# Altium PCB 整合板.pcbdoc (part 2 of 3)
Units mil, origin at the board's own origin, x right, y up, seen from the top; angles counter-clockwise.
Board outline 5095 x 5568.76 mil, 2 copper layers (Top Layer, Bottom Layer); 124 components, 78 nets, 425 pads, 497 vias.
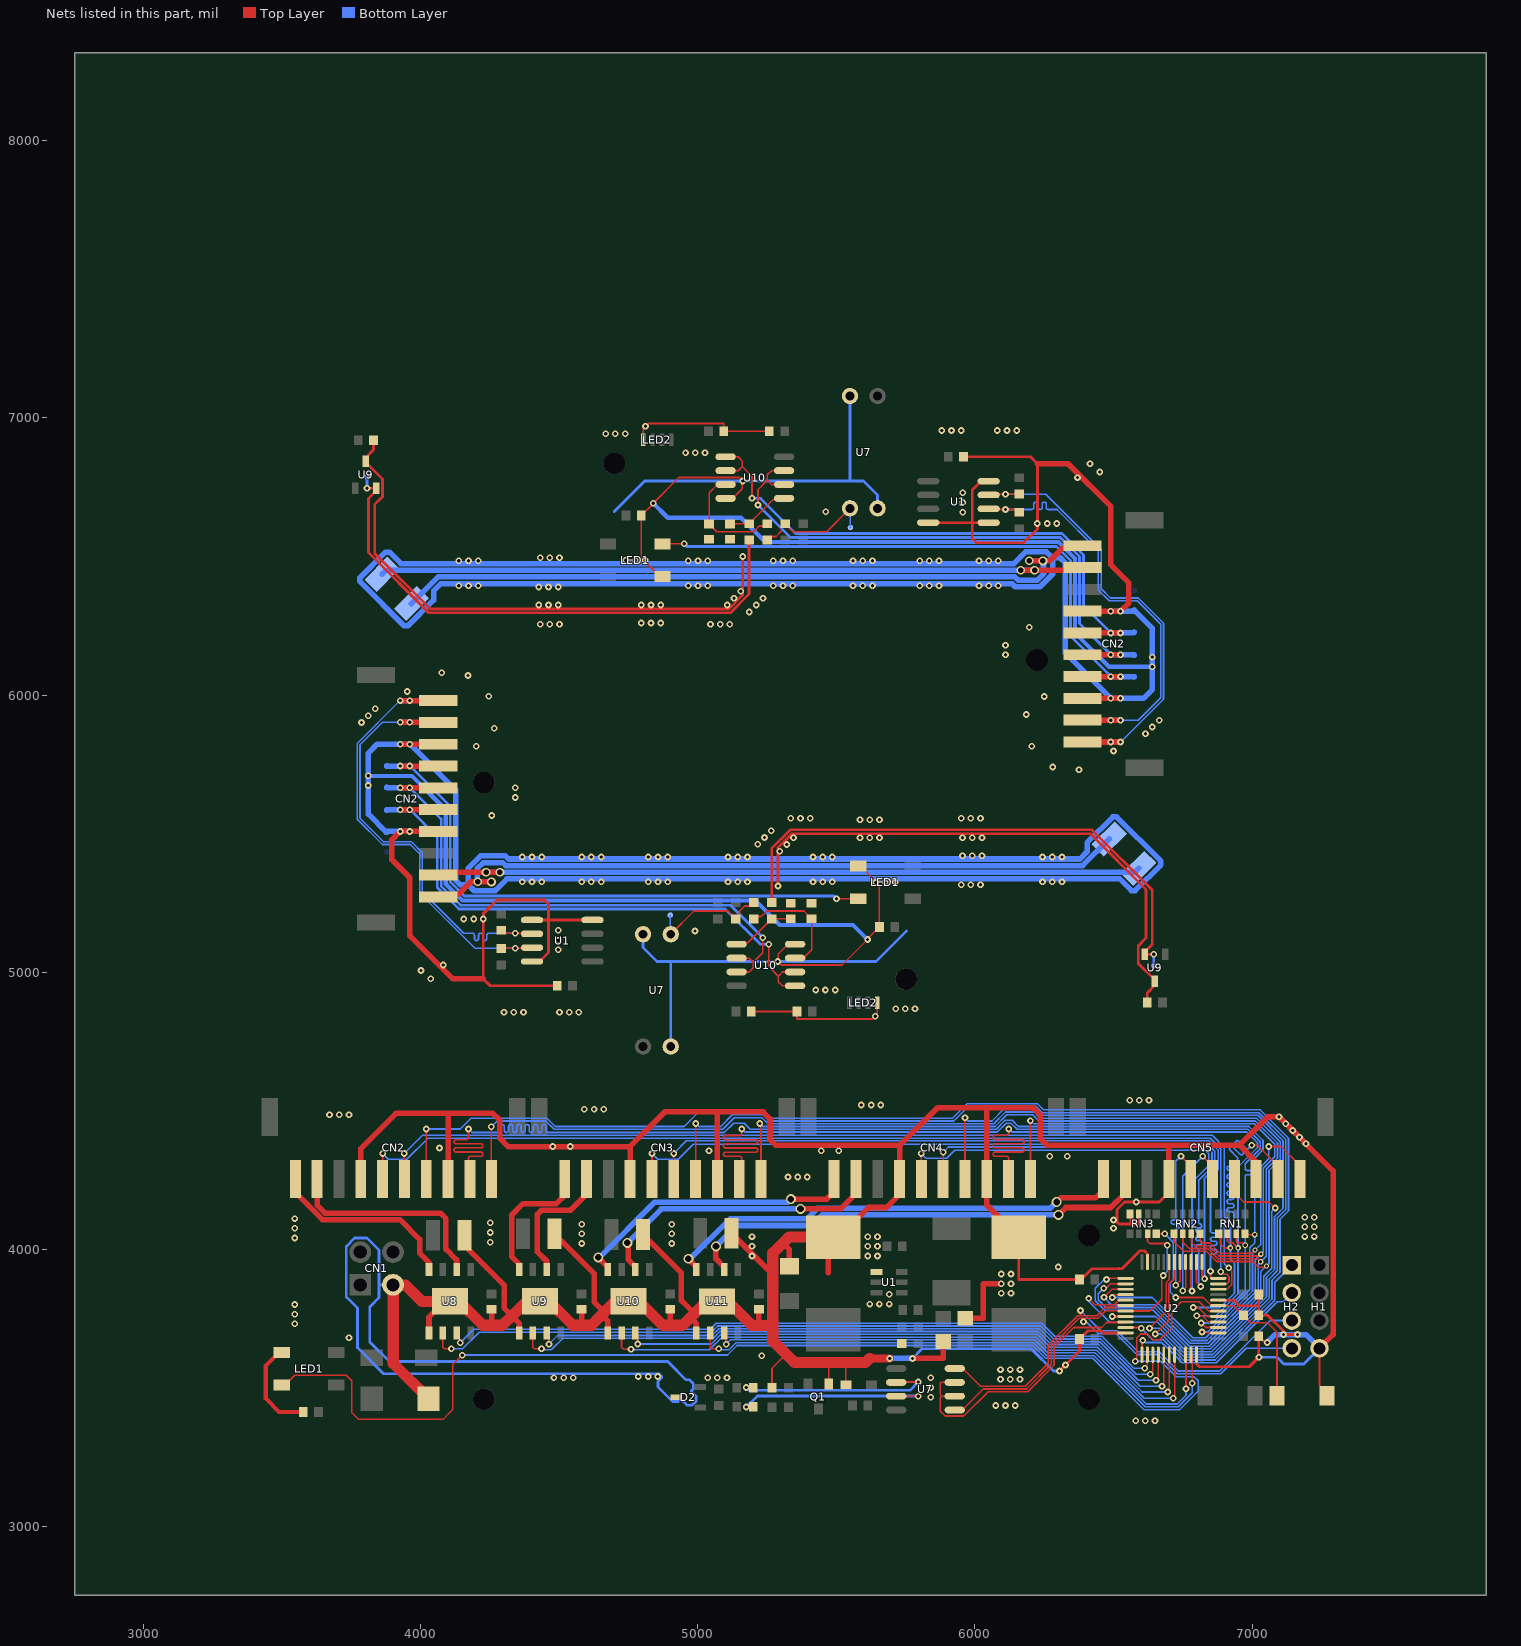
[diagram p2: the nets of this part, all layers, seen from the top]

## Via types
v1: diameter 24.02, hole 12.01, Top Layer to Bottom Layer, 450 vias
v2: diameter 36, hole 24, Top Layer to Bottom Layer, 28 vias
v3: diameter 32, hole 20, Top Layer to Bottom Layer, 8 vias
v4: diameter 19.68, hole 11.81, Top Layer to Bottom Layer, 8 vias
v5: diameter 40, hole 24, Top Layer to Bottom Layer, 3 vias

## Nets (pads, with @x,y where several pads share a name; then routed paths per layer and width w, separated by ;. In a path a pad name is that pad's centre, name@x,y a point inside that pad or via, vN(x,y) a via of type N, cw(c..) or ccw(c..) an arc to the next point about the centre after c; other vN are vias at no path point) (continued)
GND: C2.1 C3.1 C4.1 C6.1 C7.1 C8.1 C9.1 C10.1 C11.1 C12.1 C13.1 C14.1 C15.1 C16.1 CN1.2 CN2.3 CN2.7 CN3.3 CN3.7 CN4.3 CN4.7 CN5.3 CN5.7 D1.1 D2.3 D3.1 GND.1 H1.4 LED1.3 LED2.1 Q1.1 R2.1@5736,3659.34 R3.2@4156.74,4050 R4.2@4481.74,4054.68 R5.2@4801.74,4052.34 R6.2@5121.74,4057.02 R10.1 RN3.7 RN3.8 SW1.2 U1.1@5644.76,3917.4 U1.4@4619.22,5188.02 U1.4@5831.16,6622.22 U1.5@4400.92,5188.02 U1.5@6049.46,6622.22 U1.8 U2.8 U2.23 U2.35 U2.47 U5.1@5488.3,4043.23 U6.1 U7.2@4901.8,4730.81 U7.2@5548.58,7079.42 U7.4@4801.8,5136.31 U7.4@5648.58,6673.92 U8.1 U8.9 U9.1@4354.08,3696.77 U9.3@3800.94,6843.55 U9.3@6649.44,4966.68 U9.9 U10.1@4674.08,3696.81 U10.4@5099.7,6709.93 U10.4@5350.68,5100.31 U10.9 U11.1 U11.9 | length 51753.8
  Top Layer w6: LED2.1@4802.99,6921.42 4802.99,6962.61 4820.31,6979.93 5092.87,6979.93 C9.1@5092.87,6952.44 C8.1@5257.75,6952.44 ; LED1.3@4872.12,6427.42 4863.92,6427.42 4795.43,6495.91 C7.1@4795.43,6647.72 4838.1,6690.39 v1(4838.1,6692.72) 4930.31,6784.93 5150.31,6784.93 5160.31,6774.93 5160.31,6744.93 5125.31,6709.93 U10.4@5099.7,6709.93 ; C8.1@5192.63,4857.8 C9.1@5357.51,4857.79 5357.51,4830.31 5630.07,4830.31 5647.39,4847.63 LED2.1@5647.39,4888.81 ; R10.1@5267.54,3500 5267.54,3570.03 5317.85,3620.35 ; U10.4@5350.68,5100.31 5325.07,5100.31 5290.07,5065.31 5290.07,5035.31 5300.07,5025.31 5520.07,5025.31 v1(5612.28,5117.52) 5612.28,5119.85 C7.1@5654.95,5162.52 5654.95,5314.32 5586.46,5382.81 LED1.3@5578.26,5382.81 ; Q1.1@5472.4,3512.85 5472.4,3589.35 5473.05,3590 ; 5532.87,3590 5533.84,3589.04 D3.1@5533.84,3510 ; 6559.9,4090 RN3.8@6559.9,4126.37 ; 6591.39,4090 RN3.7@6591.39,4126.37 ; H1.4@7243.61,3641.82 7243.61,3506.39 7271.1,3478.9 SW1.2@7271.1,3470
  Top Layer w10: C10.1@3828.5,6919.93 3828.5,6885.26 3800.94,6857.69 U9.3@3800.94,6843.55 3800.94,6839.3 3861.13,6779.1 3861.13,6715.75 3833,6687.62 3833,6511.87 4033.93,6310.95 5111.32,6310.95 5161.4,6361.02 v1(5161.4,6499.93) ; U1.8@4400.92,5038.02 4427.78,5038.02 4460.07,5070.31 4460.07,5188.02 ; U1.5@4400.92,5188.02 4460.07,5188.02 ; C6.1@4492.2,4950.31 4250.07,4950.31 4225.07,4975.31 v1(4225.07,5191.2) 4225.07,5210.31 4275.07,5260.31 4445.07,5260.31 4460.07,5245.31 4460.07,5188.02 ; U1.4@4619.22,5188.02 4460.07,5188.02 ; v1(5288.98,5310.31) 5288.98,5449.21 5339.06,5499.28 6416.45,5499.28 6617.38,5298.36 6617.38,5122.61 6589.25,5094.48 6589.25,5031.13 6649.44,4970.94 U9.3@6649.44,4966.68 6649.44,4952.54 6621.88,4924.98 C10.1@6621.88,4890.31 ; U1.4@5831.16,6622.22 5990.31,6622.22 ; C6.1@5958.18,6859.93 6200.31,6859.93 6225.31,6834.93 v1(6225.31,6619.04) 6225.31,6599.93 6175.31,6549.93 6005.31,6549.93 5990.31,6564.93 5990.31,6622.22 ; U1.5@6049.46,6622.22 5990.31,6622.22 ; U1.8@6049.46,6772.22 6022.6,6772.22 5990.31,6739.93 5990.31,6622.22 ; U6.1@6157.59,4043.23 6157.59,3890 C9.1@6377.44,3890 6383.56,3890 6422.58,3929.02 6521.83,3929.02 ; v1(6305,3560) v1(6326.69,3581.69) 6377.44,3632.44 C10.1@6377.44,3675 6407.44,3705 6455,3705 6462.62,3697.38 U2.35@6543.71,3697.38 ; 6520,3930.84 6521.83,3929.02 ; 6591.39,4090 6559.9,4090 6520,4090 6512.93,4097.07 6512.93,4142.93 6540,4170 v1(6581.82,4170) 6665,4170 6700.12,4205.12 CN5.7@6700.12,4252.8 ; U2.23@6622.45,3953.28 6622.45,3982.55 6611.21,3993.79 6595.69,3993.79 6530.91,3929.02 6521.83,3929.02 ; U2.47@6799.61,3618.64 6799.61,3585.39 6810,3575 6990,3575 7024.41,3609.41 C8.1@7024.41,3685.29 7046.89,3662.81 v1(7054.99,3662.81) ; U2.8@6878.35,3815.49 6934.51,3815.49 6955,3795 7024.41,3795 ; C7.1@7024.41,3835.93 7024.41,3795 ; v1(7164.47,3691.27) v1(7113.72,3691.27) 7113.72,3703.8 7056.59,3760.93 C6.1@7024.41,3760.93 7024.41,3795
  Top Layer w15: LED1.3@3497.61,3627.13 3487.13,3627.13 3440,3580 3440,3460 3487.88,3412.12 C11.1@3575.41,3412.12
  Top Layer w20: CN2.7@3782.8,4252.8 3782.8,4362.8 3910,4490 4099.41,4490 ; v1(3925.07,5822.41) v1(3960.07,5822.41) CN2.3@4062.29,5822.41 ; U8.1@4029.08,3696.85 4029.08,3754.08 U8.9@4086.35,3811.35 ; CN2.7@4062.29,5507.45 v1(3960.07,5507.45) v1(3925.07,5507.45) 3895.07,5477.45 3895.07,5405.31 3960.07,5340.31 3960.07,5130.31 4115.07,4975.31 4225.07,4975.31 ; CN2.3@4097.76,4252.8 4097.76,4488.34 4099.41,4490 ; R3.2@4156.74,4050 4156.74,4013.26 4300,3870 4300,3787.01 4328.5,3758.5 4354.08,3732.93 U9.1@4354.08,3696.77 ; C13.1@4255,3782.44 4255,3728.4 4258.4,3725 ; R4.2@4481.74,4054.68 4625,3911.42 4625,3808.85 4661.93,3771.93 ; 4580,3724.97 C15.1@4580,3782.52 ; 4652.39,3762.39 4674.08,3740.71 U10.1@4674.08,3696.81 ; CN3.7@4755.24,4252.8 4755.24,4370 ; R5.2@4801.74,4052.34 4940,3914.08 4940,3813.76 4986.88,3766.88 ; C14.1@4900,3782.48 4900,3725.52 4900.68,3724.84 ; 4980,3745 4994.08,3730.92 U11.1@4994.08,3696.73 ; CN3.3@5070.2,4252.8 5070.2,4492.07 5073.13,4495 ; R6.2@5121.74,4057.02 5270,3908.76 ; C16.1@5220,3782.57 5220,3726.32 5221.56,3724.76 ; 5307.04,4022.04 5330,3999.08 C2.1@5330,3937.7 ; 5470,3914.37 5470,4024.94 U5.1@5488.3,4043.23 5508.23,4043.23 5615,4150 5680,4150 5727.68,4197.68 CN4.7@5727.68,4252.8 5727.68,4372.68 5730,4375 ; v1(5774.24,3605) 5885.63,3605 C3.1@5885.63,3667.88 ; C4.1@5964.37,3750 6030,3750 6030,3875 v1(6095,3875) ; U6.1@6157.59,4043.23 6042.64,4158.18 CN4.3@6042.64,4252.8 6042.64,4509.19 6041.83,4510 ; 6225.31,6834.93 6335.31,6834.93 6490.31,6679.93 6490.31,6469.93 6555.31,6404.93 6555.31,6332.78 v1(6525.31,6302.78) v1(6490.31,6302.78) CN2.7@6388.09,6302.78 ; CN2.3@6388.09,5987.82 v1(6490.31,5987.82) v1(6525.31,5987.82) ; CN5.7@6700.12,4252.8 6700.12,4373.66 6698.77,4375 ; CN5.3@7015.08,4252.8 7015.08,4314.92 6955,4375 ; H1.4@7243.61,3641.82 7293.06,3691.27 7293.06,4281.94 v1(7195,4380) v1(7171.28,4403.72) v1(7147.06,4427.94) v1(7122.26,4452.74) v1(7097.46,4477.54) 7057.54,4477.54 6955,4375 ; 4099.41,4490 4260,4490 4285,4465 4285,4400 4315,4370 v1(4475.31,4370) v1(4538.74,4370) 4755.24,4370 ; 4755.24,4370 4755.24,4370.24 4880,4495 5073.13,4495 ; 5073.13,4495 5235,4495 5260,4470 5260,4395 5280,4375 5730,4375 ; 5730,4375 5865,4510 6041.83,4510 ; 6041.83,4510 6210,4510 6235,4485 6235,4400 6260,4375 6698.77,4375 ; 6698.77,4375 6955,4375
  Top Layer w30: 5620,3605 v1(5692.07,3605)
  Top Layer w40: D1.1@4027.02,3460 3900,3587.02 3900,3870 CN1.2@3899.05,3870.95 3944.05,3870.95 4003.65,3811.35 4086.35,3811.35 U8.9@4104.08,3811.35 4136.76,3811.35 4223.11,3725 4258.4,3725 4295,3725 4328.5,3758.5 4381.27,3811.27 U9.9@4429.08,3811.27 4461.76,3811.27 4548.11,3724.92 4580.05,3724.92 4614.92,3724.92 4652.39,3762.39 4661.93,3771.93 4701.19,3811.19 4786.76,3811.19 4873.11,3724.84 4900.68,3724.84 4944.84,3724.84 4986.88,3766.88 5031.11,3811.11 5108.89,3811.11 5195.24,3724.76 5221.56,3724.76 5270,3724.76 ; U5.1@5488.3,4043.23 5328.23,4043.23 5307.04,4022.04 5270,3985 5270,3908.76 5270,3724.76 ; 5620,3605 5605,3590 5532.87,3590 5473.05,3590 5348.19,3590 5317.85,3620.35 5270,3668.19 5270,3724.76
  Bottom Layer w10: CN1.2@3899.05,3870.95 3898.71,3871.29 3848.7,3871.29 ; 4697.87,6662.49 4807.87,6772.49 v1(5161.82,6772.49) 5548.58,6772.49 ; U7.4@4801.8,5136.31 4801.8,5088.58 4852.63,5037.75 4901.8,5037.75 ; U7.2@4901.8,4730.81 4901.8,5037.75 ; U7.2@5548.58,7079.42 5548.58,6772.49 ; U7.4@5648.58,6673.92 5648.58,6721.66 5597.75,6772.49 5548.58,6772.49 ; 5752.51,5147.75 5642.51,5037.75 v1(5288.56,5037.75) 4901.8,5037.75 ; v1(5774.24,3605) 5809.24,3640 6203.01,3640 6283.01,3560 v1(6305,3560) v1(6326.69,3581.69) ; v1(7025.25,3609.75) 7089.75,3609.75 ; 7090,3610 7089.75,3609.75 ; H1.4@7243.61,3641.82 7186.8,3585 7114.5,3585 7089.75,3609.75 ; 3848.7,3871.29 3848.7,3824.61 3815,3790.9 3815,3665 3885.98,3594.02 4890.81,3594.02 4956.83,3527.99 4969.52,3527.99 4982.99,3514.52 4982.99,3495.48 4976.26,3488.74 4976.26,3485.27 4992.5,3469.03 4992.5,3449.98 4979.03,3436.52 4959.98,3436.52 4938.64,3457.86 4937.14,3457.86 4928.64,3449.36 4908.58,3449.36 4855.78,3502.16 4855.78,3522.31 4868.97,3535.41 4868.97,3540.22 4859.19,3550 3865,3550 3770.98,3644.02 3770.98,3786.63 3730.59,3827.03 3730.59,4009.91 3760.09,4039.41 3805.59,4039.41 3848.7,3996.3 3848.7,3871.29
  Bottom Layer w15: v1(3810.07,5708.28) 3967.1,5708.28 4089.54,5585.84 4089.54,5317.72 4149.47,5257.79 5207.59,5257.79 5295.07,5170.31 5559.5,5170.31 v1(5612.28,5117.52) ; v1(4838.1,6692.72) 4890.89,6639.93 5155.31,6639.93 5242.79,6552.44 6300.91,6552.44 6360.84,6492.51 6360.84,6224.39 6483.28,6101.96 v1(6640.31,6101.96)
  Bottom Layer w20: v1(3960.07,5507.45) v1(3925.07,5507.45) 3879.46,5507.45 GND.1@3876.06,5504.05 3810.07,5570.04 v1(3810.07,5673.28) v1(3810.07,5708.28) 3810.07,5790.31 3842.18,5822.41 v1(3925.07,5822.41) v1(3960.07,5822.41) 4125.07,5657.41 4125.07,5332.44 4142.69,5314.82 4170.98,5314.82 ; v1(5692.07,3605) v1(5774.24,3605) ; v1(6490.31,6302.78) v1(6525.31,6302.78) 6570.93,6302.78 GND.1@6574.32,6306.18 6640.31,6240.2 v1(6640.31,6136.96) v1(6640.31,6101.96) 6640.31,6019.93 6608.2,5987.82 v1(6525.31,5987.82) v1(6490.31,5987.82) 6325.31,6152.82 6325.31,6477.79 6307.69,6495.41 6279.4,6495.41 ; v1(7054.99,3662.81) 7083.45,3691.27 v1(7113.72,3691.27) v1(7164.47,3691.27) 7194.16,3691.27 H1.4@7243.61,3641.82 ; v1(7097.46,4477.54) v1(7122.26,4452.74) v1(7147.06,4427.94) v1(7171.28,4403.72) v1(7195,4380) ; 4170.98,5314.82 4170.07,5315.73 4170.07,5374.17 4215.23,5419.32 4304.92,5419.32 4316.24,5408.01 6378.58,5408.01 6404.71,5434.13 6404.71,5467.31 6497.59,5560.19 6510.83,5560.19 6670.8,5400.23 6670.8,5386.98 6577.92,5294.1 6564.67,5294.1 6522.82,5335.96 4310.07,5335.96 4286.41,5312.29 4286.41,5312.06 4267.67,5293.32 4192.48,5293.32 4170.98,5314.82 ; 6279.4,6495.41 6280.31,6494.51 6280.31,6436.06 6235.15,6390.91 6145.46,6390.91 6134.14,6402.23 4071.8,6402.23 4045.68,6376.1 4045.68,6342.92 3952.8,6250.04 3939.55,6250.04 3779.59,6410.01 3779.59,6423.25 3872.46,6516.13 3885.71,6516.13 3927.56,6474.28 6140.31,6474.28 6163.97,6497.94 6163.97,6498.17 6182.71,6516.91 6257.9,6516.91 6279.4,6495.41
  other v1: 6580,3380 6615,3380 6650,3380 6075,3435 6110,3435 6145,3435 5840,3465 5840,3500 6092.37,3529.87 6127.37,3529.87 6162.37,3529.87 4480,3535 4515,3535 4550,3535 5035,3535 5070,3535 5105,3535 5840,3535 4785,3540 4820,3540 4855,3540 6092.37,3564.87 6127.37,3564.87 6162.37,3564.87 5230,3615 3740,3680 3545,3730 3545,3765 3545,3800 5620,3801.35 5655,3801.35 5690,3801.35 5690,3836.35 6095,3840 6130,3840 6130,3875 6095,3910 6130,3910 6300,3935 5195,3975 5612.91,3974.89 5647.91,3974.89 5195,4010 5612.91,4009.89 5647.91,4009.89 4580,4020 4905,4020 4250,4025 3545,4040 5195,4045 5612.91,4044.89 5647.91,4044.89 7190,4045 7225,4045 4580,4055 4905,4055 4250,4060 3545,4075 6500,4075 7190,4080 7225,4080 4580,4090 4905,4090 4250,4095 6500,4105 3545,4110 7190,4115 7225,4115 5325,4260 5360,4260 5395,4260 6270,4335 6333.43,4335 5040,4355 5445,4355 5508.43,4355 4066.97,4365 3670,4485 3705,4485 3740,4485 4590,4505 4625,4505 4660,4505 5590,4520 5625,4520 5660,4520 6558.45,4536.66 6593.45,4536.66 6628.45,4536.66 5640.04,4840.28 4300.07,4855.31 4335.07,4855.31 4370.07,4855.31 4500.07,4855.31 4535.07,4855.31 4570.07,4855.31 5713.41,4867.39 5748.41,4867.39 5783.41,4867.39 5425.07,4935.31 5460.07,4935.31 5495.07,4935.31 4035.07,4975.31 4000.07,5005.31 4080.07,5025.31 4495.07,5080.31 4495.07,5115.31 4989.03,5148.13 4495.07,5150.31 4155.07,5191.2 4190.07,5191.2 5950.07,5315.31 5985.07,5315.31 6020.07,5315.31 5641.44,5323.26 5676.44,5323.26 5711.44,5323.26 4366.01,5325.31 4401.01,5325.31 4436.01,5325.31 4580.32,5325.31 4615.32,5325.31 4650.32,5325.31 4820.49,5325.31 4855.49,5325.31 4890.49,5325.31 5108.6,5325.31 5143.6,5325.31 5178.6,5325.31 5415.07,5325.31 5450.07,5325.31 5485.07,5325.31 6243.9,5325.31 6278.9,5325.31 6313.9,5325.31 4366.01,5415.31 4401.01,5415.31 4436.01,5415.31 4580.32,5415.31 4615.32,5415.31 4650.32,5415.31 4820.49,5415.31 4855.49,5415.31 4890.49,5415.31 5108.6,5415.31 5143.6,5415.31 5178.6,5415.31 5415.07,5415.31 5450.07,5415.31 5485.07,5415.31 6243.9,5415.31 6278.9,5415.31 6313.9,5415.31 5955.07,5420.31 5990.07,5420.31 6025.07,5420.31 5295.58,5435.81 5215.58,5460.81 5320.33,5460.56 5345.07,5485.31 5585.07,5485.31 5620.07,5485.31 5655.07,5485.31 5955.07,5485.31 5990.07,5485.31 6025.07,5485.31 5240.33,5485.56 5265.07,5510.31 5585.07,5550.31 5620.07,5550.31 5655.07,5550.31 5335.07,5555.31 5370.07,5555.31 5405.07,5555.31 5950.07,5555.31 5985.07,5555.31 6020.07,5555.31 4255.07,5565.31 4340.07,5630.31 4340.07,5665.31 6375.31,5729.93 6280.31,5739.93 6500.29,5797.73 6205.31,5814.93 4199.82,5815.56 6615.31,5859.93 4265.07,5880.31 6640.06,5884.67 3785.58,5900.81 6664.8,5909.42 3810.33,5925.56 6185.31,5929.93 3835.07,5950.31 4245.07,5995.31 6250.56,5994.67 3950.09,6012.5 4170.07,6070.31 4075.07,6080.31 6110.31,6144.93 6110.31,6179.93 6195.31,6244.93 4430.31,6254.93 4465.31,6254.93 4500.31,6254.93 5045.31,6254.93 5080.31,6254.93 5115.31,6254.93 4795.31,6259.93 4830.31,6259.93 4865.31,6259.93 5185.31,6299.93 4425.31,6324.93 4460.31,6324.93 4495.31,6324.93 4795.31,6324.93 4830.31,6324.93 4865.31,6324.93 5105.31,6324.93 5210.06,6324.67 5234.8,6349.42 5130.06,6349.67 5154.8,6374.42 4425.31,6389.93 4460.31,6389.93 4495.31,6389.93 4136.48,6394.93 4171.48,6394.93 4206.48,6394.93 4965.31,6394.93 5000.31,6394.93 5035.31,6394.93 5271.78,6394.93 5306.78,6394.93 5341.78,6394.93 5559.89,6394.93 5594.89,6394.93 5629.89,6394.93 5800.06,6394.93 5835.06,6394.93 5870.06,6394.93 6014.37,6394.93 6049.37,6394.93 6084.37,6394.93 4136.48,6484.93 4171.48,6484.93 4206.48,6484.93 4965.31,6484.93 5000.31,6484.93 5035.31,6484.93 5271.78,6484.93 5306.78,6484.93 5341.78,6484.93 5559.89,6484.93 5594.89,6484.93 5629.89,6484.93 5800.06,6484.93 5835.06,6484.93 5870.06,6484.93 6014.37,6484.93 6049.37,6484.93 6084.37,6484.93 4738.94,6486.97 4773.94,6486.97 4808.94,6486.97 4430.31,6494.93 4465.31,6494.93 4500.31,6494.93 6260.31,6619.04 6295.31,6619.04 5955.31,6659.93 5461.36,6662.1 5955.31,6694.93 5955.31,6729.93 6370.31,6784.93 6450.31,6804.93 6415.31,6834.93 4955.31,6874.93 4990.31,6874.93 5025.31,6874.93 4666.97,6942.84 4701.97,6942.84 4736.97,6942.84 5880.31,6954.93 5915.31,6954.93 5950.31,6954.93 6080.31,6954.93 6115.31,6954.93 6150.31,6954.93 4810.34,6969.96
HALL_OUT: Hall.1 R5.1@5184.39,6559.1 R5.1@5265.99,5251.13 U9.2@3838.34,6746.3 U9.2@6612.04,5063.93 | length 4008.6
  Top Layer w10: v1(3805.31,6746.3) U9.2@3838.34,6746.3 3838.34,6737.96 3810.21,6709.82 3810.21,6514.85 4028.12,6296.93 5117.13,6296.93 5184.39,6364.2 R5.1@5184.39,6559.1 ; R5.1@5265.99,5251.13 5265.99,5446.04 5333.25,5513.3 6422.26,5513.3 6640.18,5295.38 6640.18,5100.41 6612.04,5072.28 U9.2@6612.04,5063.93 v1(6645.07,5063.93)
  Bottom Layer w10: v1(3805.31,6746.3) 3805.31,6787.11 Hall.1@3805.41,6787.21 ; Hall.1@6644.97,5023.02 6645.07,5023.13 v1(6645.07,5063.93)
HALL_RC: C11.2@5115.31,6617.48 C11.2@5335.07,5192.75 R5.2@5184.39,6618.42 R5.2@5265.99,5191.81 U10.5@5139.46,5100.31 U10.5@5310.92,6709.93 | length 467.8
  Top Layer w6: C11.2@5115.31,6617.48 5116.25,6618.42 R5.2@5184.39,6618.42 5270.9,6704.93 5305.92,6704.93 U10.5@5310.92,6709.93 ; U10.5@5139.46,5100.31 5144.46,5105.31 5179.48,5105.31 R5.2@5265.99,5191.81 5334.13,5191.81 C11.2@5335.07,5192.75
IR1_RC: C12.2 R6.1@5200.99,5191.81 R6.1@5249.39,6618.42 U10.3@5099.7,6759.93 U10.3@5350.68,5050.31 | length 833.4
  Top Layer w6: U10.3@5099.7,6759.93 5070.31,6759.93 5040.19,6729.81 C12.2@5040.19,6617.48 5067.75,6589.93 5201.49,6589.93 5221.49,6609.93 5240.9,6609.93 R6.1@5249.39,6618.42 ; R6.1@5200.99,5191.81 5209.48,5200.31 5228.9,5200.31 5248.9,5220.31 5382.63,5220.31 C12.2@5410.19,5192.75 5410.19,5080.42 5380.07,5050.31 U10.3@5350.68,5050.31
IR1_RECV: IR1.1 R4.2@5135.99,5191.81 R4.2@5314.39,6618.42 R6.2@5200.99,5251.13 R6.2@5249.39,6559.1 U7.3@4901.8,5136.31 U7.3@5548.58,6673.92 | length 896.8
  Top Layer w6: U7.3@4901.8,5136.31 4985.78,5220.31 5107.5,5220.31 R4.2@5135.99,5191.81 5150,5205.82 5150,5219.55 5168.74,5238.29 5188.15,5238.29 R6.2@5200.99,5251.13 ; R6.2@5249.39,6559.1 5262.23,6571.94 5281.65,6571.94 5300.38,6590.68 5300.38,6604.41 R4.2@5314.39,6618.42 5342.88,6589.93 5464.6,6589.93 U7.3@5548.58,6673.92
  Bottom Layer w6: IR1.1@4900.07,5205.63 4900.07,5138.06 U7.3@4901.8,5136.31 ; U7.3@5548.58,6673.92 5550.31,6672.17 IR1.1@5550.31,6604.6
K_ONLINE: CN2.6@4062.29,5586.19 CN2.6@6388.09,6224.04 Online.1 U10.1@5099.7,6859.93 U10.1@5350.68,4950.31 U10.2@5099.7,6809.93 U10.2@5350.68,5000.31 | length 4216.5
  Top Layer w6: U10.2@5099.7,6809.93 5145.31,6809.93 5160.31,6824.93 ; U10.1@5099.7,6859.93 5145.31,6859.93 5160.31,6844.93 5160.31,6824.93 ; v1(5195.31,6709.93) 5195.31,6789.93 5160.31,6824.93 ; v1(5255.07,5100.31) 5255.07,5020.31 5290.07,4985.31 ; U10.1@5350.68,4950.31 5305.07,4950.31 5290.07,4965.31 5290.07,4985.31 ; U10.2@5350.68,5000.31 5305.07,5000.31 5290.07,4985.31
  Top Layer w20: v1(3925.07,5586.19) v1(3960.07,5586.19) CN2.6@4062.29,5586.19 ; CN2.6@6388.09,6224.04 v1(6490.31,6224.04) v1(6525.31,6224.04)
  Bottom Layer w10: v1(3960.07,5586.19) 4059.01,5487.26 4059.01,5305.08 4136.83,5227.26 5098.12,5227.26 5225.07,5100.31 v1(5255.07,5100.31) ; v1(5195.31,6709.93) 5225.31,6709.93 5352.26,6582.97 6313.55,6582.97 6391.37,6505.16 6391.37,6322.98 v1(6490.31,6224.04)
  Bottom Layer w20: Online.1@3876.06,5584.05 3878.16,5586.19 v1(3925.07,5586.19) v1(3960.07,5586.19) ; v1(6490.31,6224.04) v1(6525.31,6224.04) 6572.23,6224.04 Online.1@6574.32,6226.14
K_ONLINE1: CN2.6@3861.54,4252.8 U2.11 | length 3715
  Top Layer w6: CN2.6@3861.54,4252.8 v1(3861.54,4345) ; U2.11@6878.35,3874.54 6909.54,3874.54 6916.86,3881.86 6916.86,3900.15 6908.48,3908.53 6896.92,3908.53 v1(6887.64,3917.81)
  Bottom Layer w6: v1(3861.54,4345) 3882.53,4324.01 3948.97,4324.01 4025.38,4400.41 6849.1,4400.41 6887.59,4361.92 v1@6887.59,3917.85
K_ONLINE2: CN3.6 U2.13 | length 2704.5
  Top Layer w6: CN3.6@4833.98,4252.8 v1(4833.98,4345) ; U2.13@6819.3,3953.28 6819.3,3902.74 v1(6828.82,3893.22)
  Bottom Layer w6: v1(4833.98,4345) 4854.97,4324.01 4929.01,4324.01 4983.41,4378.41 6839.99,4378.41 6865.59,4352.81 6865.59,4292.19 6828.82,4255.42 v1(6828.82,3893.22)
K_ONLINE3: CN4.6 U2.15 | length 1779.3
  Top Layer w6: CN4.6@5806.42,4252.8 v1(5806.42,4345) ; U2.15@6779.93,3953.28 6779.93,3852.25 v1(6783.59,3848.59)
  Bottom Layer w6: v1(5806.42,4345) 5823.08,4328.34 5898.34,4328.34 5926.41,4356.41 6830.88,4356.41 6843.59,4343.7 6843.59,4301.3 6783.59,4241.3 v1(6783.59,3848.59)
K_ONLINE4: CN5.6 U2.17 | length 701.7
  Top Layer w6: v1(6725.28,3869.72) 6740.56,3885 U2.17@6740.56,3953.28 ; v1(6743.86,4335) 6778.86,4300 CN5.6@6778.86,4252.8
  Bottom Layer w6: v1(6725.28,3869.72) 6725.28,4068.36 cw(c6731.65,4068.36) 6731.65,4074.73 ccw(c6731.65,4081.1) 6738.02,4081.1 6738.02,4083.36 ccw(c6731.65,4083.36) 6731.65,4089.73 6715.52,4089.73 cw(c6715.52,4097.23) 6715.52,4104.73 6717.78,4104.73 ccw(c6717.78,4112.23) 6725.28,4112.23 6725.28,4316.42 v1(6743.86,4335)
K_PULL: CN2.5@4062.29,5664.93 CN2.5@6388.09,6145.3 Pressure.1 U10.6@5139.46,5050.31 U10.6@5310.92,6759.93 U10.7@5139.46,5000.31 U10.7@5310.92,6809.93 | length 4234.5
  Top Layer w6: U10.7@5139.46,5000.31 5185.07,5000.31 5200.07,5015.31 5200.07,5035.31 ; U10.6@5139.46,5050.31 5185.07,5050.31 5200.07,5035.31 ; v1(5216.55,6686.17) 5216.55,6741.17 5250.31,6774.93 ; v1(5233.83,5124.07) 5233.83,5069.07 5200.07,5035.31 ; U10.6@5310.92,6759.93 5265.31,6759.93 5250.31,6774.93 ; U10.7@5310.92,6809.93 5265.31,6809.93 5250.31,6794.93 5250.31,6774.93
  Top Layer w20: v1(3925.07,5664.93) v1(3960.07,5664.93) CN2.5@4062.29,5664.93 ; CN2.5@6388.09,6145.3 v1(6490.31,6145.3) v1(6525.31,6145.3)
  Bottom Layer w10: v1(3960.07,5664.93) 4073.03,5551.98 4073.03,5310.88 4142.63,5241.28 5116.62,5241.28 v1(5233.83,5124.07) ; v1(5216.55,6686.17) 5333.76,6568.96 6307.75,6568.96 6377.35,6499.35 6377.35,6258.25 v1(6490.31,6145.3)
  Bottom Layer w20: Pressure.1@3876.06,5666.38 3877.51,5664.93 v1(3925.07,5664.93) v1(3960.07,5664.93) ; v1(6490.31,6145.3) v1(6525.31,6145.3) 6572.88,6145.3 Pressure.1@6574.32,6143.89
K_PULL1: CN2.5@3940.28,4252.8 U2.10 | length 3683.6
  Top Layer w6: CN2.5@3940.28,4252.8 v1(3940.28,4345) ; U2.10@6878.35,3854.86 6909.86,3854.86 6926.88,3871.88 6926.88,3921 v1(6915.99,3931.88)
  Bottom Layer w6: v1(3940.28,4345) 4005.7,4410.42 6856.04,4410.42 6899.58,4366.88 6899.58,4120.35 ccw(c6907.08,4120.35) 6907.08,4112.85 6910.74,4112.85 cw(c6910.74,4105.35) 6910.74,4097.85 6907.08,4097.85 ccw(c6907.08,4090.35) 6899.58,4090.35 6899.58,3947.27 6914.96,3931.88 v1(6915.99,3931.88)
K_PULL2: CN3.5 U2.12 | length 2691
  Top Layer w6: CN3.5@4912.72,4252.8 v1(4912.72,4345) ; v1(6850,3920) 6850,3900 6855.77,3894.23 U2.12@6878.35,3894.23
  Bottom Layer w6: v1(4912.72,4345) 4958.11,4390.39 6844.95,4390.39 6877.58,4357.77 6877.58,4287.23 6850,4259.65 6850,4065.64 ccw(c6857.5,4065.64) 6857.5,4058.14 6865.9,4058.14 cw(c6865.9,4050.64) 6865.9,4043.14 6857.5,4043.14 ccw(c6857.5,4035.64) 6857.5,4028.14 6865.9,4028.14 cw(c6865.9,4020.64) 6865.9,4013.14 6857.5,4013.14 ccw(c6857.5,4005.64) 6857.5,3998.14 6865.9,3998.14 cw(c6865.9,3990.64) 6865.9,3983.14 6857.5,3983.14 ccw(c6857.5,3975.64) 6850,3975.64 v1(6850,3920)
K_PULL3: CN4.5 U2.14 | length 1767.6
  Top Layer w6: CN4.5@5885.16,4257.13 v1(5885.16,4349.34) ; U2.14@6799.61,3953.28 6799.61,3880 v1(6814.61,3865)
  Bottom Layer w6: v1(5885.16,4349.34) 5904.22,4368.39 6835.84,4368.39 6855.58,4348.66 6855.58,4296.34 6807.83,4248.59 6807.83,4095.71 ccw(c6812.72,4095.71) 6812.72,4090.81 cw(c6812.72,4085.92) 6817.62,4085.92 6817.62,4080.71 cw(c6812.72,4080.71) 6812.72,4075.81 6802.93,4075.81 ccw(c6802.93,4070.92) 6798.03,4070.92 6798.03,4065.71 ccw(c6802.93,4065.71) 6802.93,4060.81 6812.72,4060.81 cw(c6812.72,4055.92) 6817.62,4055.92 6817.62,4050.71 cw(c6812.72,4050.71) 6812.72,4045.81 6802.93,4045.81 ccw(c6802.93,4040.92) 6798.03,4040.92 6798.03,4035.71 ccw(c6802.93,4035.71) 6802.93,4030.81 6812.72,4030.81 cw(c6812.72,4025.92) 6817.62,4025.92 6817.62,4020.71 cw(c6812.72,4020.71) 6812.72,4015.81 6802.93,4015.81 ccw(c6802.93,4010.92) 6798.03,4010.92 6798.03,4005.71 ccw(c6802.93,4005.71) 6802.93,4000.81 cw(c6802.93,3995.92) 6807.83,3995.92 6807.83,3871.78 v1(6814.61,3865)
K_PULL4: CN5.5 U2.16 | length 719.3
  Top Layer w6: v1(6750,3850) 6760.24,3860.24 U2.16@6760.24,3953.28 ; v1(6822.6,4335) 6857.6,4300 CN5.5@6857.6,4252.8
  Bottom Layer w6: v1(6750,3850) 6750,4262.4 v1(6822.6,4335)
MCU_RTS: U2.33 U7.2@5926.84,3468.8 U7.3@5926.84,3518.8 | length 1058.8
  Top Layer w6: U7.2@5926.84,3468.8 5881,3468.8 ; U7.3@5926.84,3518.8 5878.8,3518.8 5875,3515 5875,3474.8 5881,3468.8 ; U2.33@6543.71,3736.75 6541.93,3734.97 6474.97,3734.97 6457.02,3717.02 6357.02,3717.02 6285.03,3645.03 6285.03,3580.03 6189.97,3484.97 6047.56,3484.97 5960.01,3397.41 5892.59,3397.41 5875,3415 5875,3462.8 5881,3468.8
MCU_RX: H2.4 RN3.3 U2.31 U7.1@5926.84,3418.8 | length 2140.1
  Top Layer w6: U7.1@5926.84,3418.8 5953.8,3418.8 6029.98,3494.98 6185.82,3494.98 6275.01,3584.18 6275.01,3649.18 6375.49,3749.65 v1@6391.54,3749.65 ; v1(6391.54,3738.01) v1@6391.54,3749.65 ; RN3.3@6622.89,4055.5 6622.89,4028.11 6631.08,4019.92 6688.27,4019.92 v1(6694.27,4013.92) ; v1(6680.2,3904.59) 6674.2,3898.59 6674.2,3819.2 6631.12,3776.12 U2.31@6543.71,3776.12 6542.41,3777.42 6471.59,3777.42 6443.82,3749.65 v1@6391.54,3749.65
  Bottom Layer w6: v1(6391.54,3738.01) 6401.16,3738.01 6443.79,3695.38 6507.76,3695.38 6584.02,3619.12 6660.51,3619.12 6730.13,3549.49 6887.23,3549.49 6979.56,3641.82 H2.4@7143.61,3641.82 ; v1(6680.2,3904.59) 6694.27,3918.67 v1(6694.27,4013.92)
MCU_SCL: CN2.1@4062.29,5979.89 CN2.1@6388.09,5830.34 R3.2@4290.07,5084.97 R3.2@6160.31,6725.27 U1.7 | length 3245.8
  Top Layer w6: R3.2@4290.07,5084.97 4290.41,5085.31 v1(4340.07,5085.31) 4398.22,5085.31 U1.7@4400.92,5088.02 ; U1.7@6049.46,6722.22 6052.17,6724.93 v1(6110.31,6724.93) 6159.97,6724.93 R3.2@6160.31,6725.27
  Top Layer w20: v1(3925.07,5979.89) v1(3960.07,5979.89) CN2.1@4062.29,5979.89 ; CN2.1@6388.09,5830.34 v1(6490.31,5830.34) v1(6525.31,5830.34)
  Bottom Layer w6: v1@3924.66,5979.89 3770.06,5825.29 3770.06,5551.16 3860.93,5460.29 3961.45,5460.29 3995.07,5426.67 3995.07,5285.31 4195.07,5085.31 v1(4340.07,5085.31) ; v1(6110.31,6724.93) 6255.31,6724.93 6455.31,6524.93 6455.31,6383.57 6488.93,6349.94 6589.46,6349.94 6680.32,6259.07 6680.32,5984.94 v1@6525.72,5830.34
  Bottom Layer w20: v1(3925.07,5979.89) v1(3960.07,5979.89) ; v1(6490.31,5830.34) v1(6525.31,5830.34)
MCU_SCL1: CN2.1@4255.24,4252.8 RN2.1 U2.25 | length 5040.6
  Top Layer w6: v1(4253.95,4441.43) 4253.95,4254.08 CN2.1@4255.24,4252.8 ; v1(6475,3890) 6479.23,3894.23 U2.25@6543.71,3894.23 ; RN2.1@6718.46,4055.5 6718.46,4026.54 6753.21,3991.79 6835.71,3991.79 6872.55,3954.95 7003.05,3954.95 7023.11,3934.89 7048.31,3934.89 v4(7052.29,3938.87)
  Bottom Layer w6: v1(4253.95,4441.43) 4274.99,4462.47 4451.06,4462.47 4481.11,4432.42 5089.29,4432.42 5131.27,4474.41 5231.37,4474.41 5253.33,4452.46 6068.27,4452.46 6110.25,4494.44 6212.96,4494.44 6234.92,4472.49 7016.36,4472.49 7101.86,4386.99 7101.86,4324.37 7061.1,4283.61 7061.1,3947.68 v4(7052.29,3938.87) 7032.11,3918.69 7032.11,3836.01 6845.75,3649.65 6773.17,3649.65 6643.62,3779.2 6468.26,3779.2 6434.53,3812.93 6434.53,3858.01 6466.51,3890 v1(6475,3890)
MCU_SCL2: CN3.1 RN2.2 U2.26 | length 3901.3
  Top Layer w6: v1(5222.68,4453.42) 5227.68,4448.42 CN3.1@5227.68,4252.8 ; v1(6465.25,3859.04) 6473.73,3859.04 6489.23,3874.54 U2.26@6543.71,3874.54 ; RN2.2@6749.95,4055.5 6749.95,4025.05 6773.19,4001.81 6839.86,4001.81 6876.7,3964.97 7019.66,3964.97 v4(7030.91,3953.72)
  Bottom Layer w6: v1(5222.68,4453.42) 5233.66,4442.44 6072.42,4442.44 6114.4,4484.42 6208.81,4484.42 6230.77,4462.47 7012.21,4462.47 7091.84,4382.84 7091.84,4328.51 7051.09,4287.76 7051.09,3973.9 v4(7030.91,3953.72) 7022.09,3944.91 7022.09,3840.16 6841.6,3659.67 6777.32,3659.67 6647.77,3789.22 6472.41,3789.22 6444.54,3817.08 6444.54,3838.34 v1(6465.25,3859.04)
MCU_SCL3: CN4.1 RN2.3 U2.27 | length 2770.3
  Top Layer w6: CN4.1@6200.12,4252.8 v1(6200.12,4463.43) ; v1(6465.54,3825.78) 6494.62,3854.86 U2.27@6543.71,3854.86 ; RN2.3@6781.45,4055.5 6781.45,4023.55 6793.18,4011.82 6844.01,4011.82 6880.85,3974.98 7025.55,3974.98 v4(7032.28,3981.72)
  Bottom Layer w6: v1(6200.12,4463.43) 6211.1,4452.46 7008.07,4452.46 7081.83,4378.7 7081.83,4332.66 7041.07,4291.91 7041.07,3990.51 v4(7032.28,3981.72) 7012.08,3961.52 7012.08,3844.31 6837.45,3669.68 6781.47,3669.68 6651.92,3799.23 6492.08,3799.23 6487.08,3804.23 6486.84,3804.23 6474.54,3816.53 6474.54,3816.77 v1(6465.54,3825.78)
MCU_SCL4: CN5.1 RN2.4 U2.28 | length 1672.6
  Top Layer w6: v1(6495.54,3825.23) 6505.48,3835.17 U2.28@6543.71,3835.17 ; RN2.4@6812.94,4055.5 6812.94,4027.06 6818.16,4021.84 6848.16,4021.84 6884.77,3985.23 6999.55,3985.23 v4(7010.87,3996.55) ; v1(7060.83,4370) 7105,4370 7172.56,4302.44 CN5.1@7172.56,4252.8
  Bottom Layer w6: v1(6495.54,3825.23) 6640.09,3825.23 6785.61,3679.7 6833.3,3679.7 7002.06,3848.46 7002.06,3987.74 v4(7010.87,3996.55) 7031.05,4016.73 7031.05,4296.05 7060.83,4325.83 v1(7060.83,4370)
MCU_SDA: CN2.2@4062.29,5901.15 CN2.2@6388.09,5909.08 R2.2@4290.07,5150.65 R2.2@6160.31,6659.59 U1.6@4400.92,5138.02 U1.6@6049.46,6672.22 | length 3253.9
  Top Layer w6: R2.2@4290.07,5150.65 4300.41,5140.31 v1(4340.07,5140.31) 4398.63,5140.31 U1.6@4400.92,5138.02 ; U1.6@6049.46,6672.22 6051.75,6669.93 v1(6110.31,6669.93) 6149.97,6669.93 R2.2@6160.31,6659.59
  Top Layer w20: v1(3925.07,5901.15) v1(3960.07,5901.15) CN2.2@4062.29,5901.15 ; CN2.2@6388.09,5909.08 v1(6490.31,5909.08) v1(6525.31,5909.08)
  Bottom Layer w6: v1(3925.07,5901.15) 3860.92,5901.15 3780.07,5820.31 3780.07,5555.31 3865.07,5470.31 3965.6,5470.31 4005.09,5430.82 4005.09,5289.46 4154.24,5140.31 4185.54,5140.31 cw(c4185.54,5132.81) 4193.04,5132.81 4193.04,5121.26 ccw(c4200.54,5121.26) 4208.04,5121.26 4208.04,5132.81 cw(c4215.54,5132.81) 4223.04,5132.81 4223.04,5121.26 ccw(c4230.54,5121.26) 4238.04,5121.26 4238.04,5132.81 cw(c4245.54,5132.81) 4245.54,5140.31 v1(4340.07,5140.31) ; v1(6110.31,6669.93) 6204.84,6669.93 ccw(c6204.84,6677.43) 6212.34,6677.43 6212.34,6688.98 cw(c6219.84,6688.98) 6227.34,6688.98 6227.34,6677.43 ccw(c6234.84,6677.43) 6242.34,6677.43 6242.34,6688.98 cw(c6249.84,6688.98) 6257.34,6688.98 6257.34,6677.43 ccw(c6264.84,6677.43) 6264.84,6669.93 6296.14,6669.93 6445.29,6520.78 6445.29,6379.42 6484.78,6339.93 6585.31,6339.93 6670.31,6254.93 6670.31,5989.93 6589.46,5909.08 v1(6525.31,5909.08)
  Bottom Layer w20: v1(3925.07,5901.15) v1(3960.07,5901.15) ; v1(6490.31,5909.08) v1(6525.31,5909.08)
MCU_SDA1: CN2.2@4176.5,4252.8 RN1.4 U2.2 | length 4674.7
  Top Layer w6: v1(4171.5,4433.39) 4171.5,4402.65 cw(c4164,4402.65) 4164,4395.15 4126.8,4395.15 ccw(c4126.8,4387.65) 4126.8,4380.15 4216.19,4380.15 cw(c4216.19,4372.65) 4216.19,4365.15 4126.8,4365.15 ccw(c4126.8,4357.65) 4126.8,4350.15 4216.19,4350.15 cw(c4216.19,4342.65) 4216.19,4335.15 4179,4335.15 ccw(c4179,4327.65) 4171.5,4327.65 4171.5,4257.8 CN2.2@4176.5,4252.8 ; v1(6819.62,3700.69) 6822.93,3697.38 U2.2@6878.35,3697.38 ; RN1.4@6974.38,4055.5 6977.65,4052.22 v4(7009.47,4052.22)
  Bottom Layer w6: v1(4171.5,4433.39) 4184.44,4420.44 4278.64,4420.44 ccw(c4278.64,4427.94) 4286.14,4427.94 4286.14,4442.34 cw(c4293.64,4442.34) 4301.14,4442.34 4301.14,4427.94 ccw(c4308.64,4427.94) 4316.14,4427.94 4316.14,4442.34 cw(c4323.64,4442.34) 4331.14,4442.34 4331.14,4427.94 ccw(c4338.64,4427.94) 4346.14,4427.94 4346.14,4442.34 cw(c4353.64,4442.34) 4361.14,4442.34 4361.14,4427.94 ccw(c4368.64,4427.94) 4376.14,4427.94 4376.14,4442.34 cw(c4383.64,4442.34) 4391.14,4442.34 4391.14,4427.94 ccw(c4398.64,4427.94) 4406.14,4427.94 4406.14,4442.34 cw(c4413.64,4442.34) 4421.14,4442.34 4421.14,4427.94 ccw(c4428.64,4427.94) 4436.14,4427.94 4436.14,4442.34 cw(c4443.64,4442.34) 4451.14,4442.34 4451.14,4427.94 ccw(c4458.64,4427.94) 4458.64,4420.44 5095.44,4420.44 5129.38,4454.38 5167.22,4454.38 5189.17,4432.42 6076.57,4432.42 6108.53,4464.39 6134.22,4464.39 6156.18,4442.44 6989.39,4442.44 7039.84,4391.99 7039.84,4358.01 7009.47,4327.64 v4(7009.47,4052.22) 7009.47,4021.77 6992.05,4004.35 6992.05,3852.61 6840.13,3700.69 v1(6819.62,3700.69)
MCU_SDA2: CN3.2 RN1.3 U2.3 | length 3626.5
  Top Layer w6: CN3.2@5148.94,4252.8 5158.52,4262.38 5158.52,4327.16 ccw(c5151.02,4327.16) 5151.02,4334.66 5099.6,4334.66 cw(c5099.6,4342.16) 5099.6,4349.66 5208.19,4349.66 ccw(c5208.19,4357.16) 5208.19,4364.66 5099.6,4364.66 cw(c5099.6,4372.16) 5099.6,4379.66 5208.19,4379.66 ccw(c5208.19,4387.16) 5208.19,4394.66 5099.6,4394.66 cw(c5099.6,4402.16) 5099.6,4409.66 5151.02,4409.66 ccw(c5151.02,4417.16) 5158.52,4417.16 v1(5158.52,4433.38) ; v1(6816.98,3733.02) 6832.94,3717.06 U2.3@6878.35,3717.06 ; RN1.3@6942.89,4055.5 6942.89,4027.11 6947.12,4022.88 6966.61,4022.88 v4(6975.31,4014.17)
  Bottom Layer w6: v1(5158.52,4433.38) 5169.5,4422.41 6080.71,4422.41 6112.68,4454.38 6130.07,4454.38 6152.03,4432.42 6985.25,4432.42 7029.83,4387.84 7029.83,4362.16 6975.31,4307.64 6975.31,4291.24 ccw(c6982.81,4291.24) 6982.81,4283.74 6991.96,4283.74 cw(c6991.96,4276.24) 6991.96,4268.74 6982.81,4268.74 ccw(c6982.81,4261.24) 6975.31,4261.24 v4(6975.31,4014.17) 6975.31,3850.04 6858.29,3733.02 v1(6816.98,3733.02)
MCU_SDA3: CN4.2 RN1.2 U2.4 | length 2539.9
  Top Layer w6: CN4.2@6121.38,4252.8 6121.38,4327.77 ccw(c6113.88,4327.77) 6113.88,4335.27 6072.85,4335.27 cw(c6072.85,4342.77) 6072.85,4350.27 6169.91,4350.27 ccw(c6169.91,4357.77) 6169.91,4365.27 6072.85,4365.27 cw(c6072.85,4372.77) 6072.85,4380.27 6169.91,4380.27 ccw(c6169.91,4387.77) 6169.91,4395.27 6072.85,4395.27 cw(c6072.85,4402.77) 6072.85,4410.27 6113.88,4410.27 ccw(c6113.88,4417.77) 6121.38,4417.77 v1(6121.38,4433.39) ; v1(6800.55,3759.01) 6820.99,3759.01 6843.25,3736.75 U2.4@6878.35,3736.75 ; RN1.2@6911.39,4055.5 6911.39,4028.61 6917.12,4022.88 6929.93,4022.88 6948.76,4004.05 v4(6949.65,4004.05)
  Bottom Layer w6: v1(6121.38,4433.39) 6132.36,4422.41 6981.1,4422.41 7019.81,4383.7 7019.81,4366.3 6949.65,4296.14 v4(6949.65,4004.05) 6949.65,3838.54 6870.12,3759.01 v1(6800.55,3759.01)
MCU_SDA4: CN5.2 RN1.1 U2.5 | length 1505.5
  Top Layer w6: v1(6788.12,3789.01) 6805.99,3789.01 6838.57,3756.43 U2.5@6878.35,3756.43 ; RN1.1@6879.9,4055.5 6885.9,4049.5 6885.9,4019.1 6900.95,4004.05 v4(6922.14,4004.05) ; v1(6998.82,4375) 7020,4375 7093.82,4301.18 CN5.2@7093.82,4252.8
  Bottom Layer w6: v1(6788.12,3789.01) 6885.95,3789.01 6936.98,3840.04 6936.98,3948.02 6922.14,3962.86 v4(6922.14,4004.05) 6922.14,4077.14 6935,4090 6935,4126.63 ccw(c6927.5,4126.63) 6927.5,4134.13 6917.09,4134.13 cw(c6917.09,4141.63) 6917.09,4149.13 6927.5,4149.13 ccw(c6927.5,4156.63) 6927.5,4164.13 6917.09,4164.13 cw(c6917.09,4171.63) 6917.09,4179.13 6927.5,4179.13 ccw(c6927.5,4186.63) 6927.5,4194.13 6917.09,4194.13 cw(c6917.09,4201.63) 6917.09,4209.13 6927.5,4209.13 ccw(c6927.5,4216.63) 6927.5,4224.13 6917.09,4224.13 cw(c6917.09,4231.63) 6917.09,4239.13 6927.5,4239.13 ccw(c6927.5,4246.63) 6927.5,4254.13 6917.09,4254.13 cw(c6917.09,4261.63) 6917.09,4269.13 6927.5,4269.13 ccw(c6927.5,4276.63) 6927.5,4284.13 6917.09,4284.13 cw(c6917.09,4291.63) 6917.09,4299.13 6927.5,4299.13 ccw(c6927.5,4306.63) 6935,4306.63 6935,4310 6946.14,4321.14 ccw(c6940.83,4326.44) 6946.14,4331.74 6921.08,4356.8 cw(c6926.38,4362.1) 6931.69,4367.41 6956.74,4342.35 ccw(c6962.05,4347.65) 6967.35,4352.96 6942.29,4378.01 cw(c6947.6,4383.32) 6952.9,4388.62 6977.96,4363.56 ccw(c6983.26,4368.87) 6988.56,4363.56 6998.82,4373.82 v1(6998.82,4375)
MCU_TX: H2.3 U2.30 U7.4@5926.84,3568.8 | length 1749
  Top Layer w6: U7.4@5926.84,3568.8 5956.2,3568.8 6020,3505 6181.67,3505 6265,3588.33 6265,3653.33 6371.34,3759.67 6381.31,3759.67 ; v1(6381.09,3778.14) 6381.09,3759.89 6381.31,3759.67 ; U2.30@6543.71,3795.8 6513.44,3795.8 6506.85,3789.22 6469.22,3789.22 6439.67,3759.67 6381.31,3759.67
  Bottom Layer w6: v1(6381.09,3778.14) 6453.84,3705.39 6511.9,3705.39 6588.16,3629.13 6664.66,3629.13 6734.28,3559.51 6883.09,3559.51 7065.39,3741.82 H2.3@7143.61,3741.82
MOTOR1_H: U2.38 U8.3 | length 2659.6
  Top Layer w6: U8.3@4129.08,3696.85 4129.08,3685.92 4142.26,3672.74 v1(4142.26,3661.94) ; v1(6612.45,3570) 6622.45,3580 U2.38@6622.45,3618.64
  Bottom Layer w6: v1(4142.26,3661.94) 4190.33,3710.02 5044.19,3710.02 5066.32,3732.14 6241.17,3732.14 6287.95,3685.36 6458.4,3685.36 6573.76,3570 v1(6612.45,3570)
MOTOR1_HOUT: CN2.9@3625.32,4252.8 U8.6 | length 779.3
  Top Layer w20: CN2.9@3625.32,4252.8 3625.32,4158.64 3653.96,4130 4070,4130 4090,4110 4090,4000 4129.08,3960.92 U8.6@4129.08,3925.85
MOTOR1_L: U2.39 U8.2 | length 2788
  Top Layer w6: U8.2@4079.08,3696.85 4079.08,3646.04 4085,3640.12 v1(4110,3640.12) ; v1(6632.44,3547.56) 6642.13,3557.25 U2.39@6642.13,3618.64
  Bottom Layer w6: v1(4110,3640.12) 4150.12,3640.12 4210,3700 5048.34,3700 5070.47,3722.13 6237.02,3722.13 6283.81,3675.34 6454.25,3675.34 6582.03,3547.56 v1(6632.44,3547.56)
MOTOR1_LOUT: CN2.10@3546.58,4252.8 U8.8 | length 690.8
  Top Layer w20: CN2.10@3546.58,4252.8 3546.58,4203.42 3644.02,4105.98 3924.02,4105.98 3995,4035 3995,3985 4029.08,3950.92 U8.8@4029.08,3925.85
MOTOR2_H: U2.40 U9.3@4454.08,3696.77 | length 2430.1
  Top Layer w6: U9.3@4454.08,3696.77 4462.2,3688.66 v1(4462.2,3656.92) ; v1(6653.65,3526.35) 6661.82,3534.52 U2.40@6661.82,3618.64
  Bottom Layer w6: v1(4462.2,3656.92) 4493.24,3687.97 5050.48,3687.97 5074.62,3712.11 6232.88,3712.11 6279.66,3665.33 6450.1,3665.33 6589.08,3526.35 v1(6653.65,3526.35)
MOTOR2_HOUT: CN3.9 U9.6 | length 476.3
  Top Layer w20: U9.6@4454.08,3925.77 4454.08,3955.92 4420,3990 4420,4125 4435,4140 4540,4140 4597.76,4197.76 CN3.9@4597.76,4252.8
MOTOR2_L: U2.41 U9.2@4404.08,3696.77 | length 2551
  Top Layer w6: U9.2@4404.08,3696.77 4404.08,3645.96 4410,3640.04 v1(4435,3640.04) ; v1(6674.86,3505.14) 6681.5,3511.77 U2.41@6681.5,3618.64
  Bottom Layer w6: v1(4435,3640.04) 4439.11,3635.93 4470.89,3635.93 4512.92,3677.96 5054.63,3677.96 5078.77,3702.09 6228.73,3702.09 6275.51,3655.31 6445.95,3655.31 6596.13,3505.14 v1(6674.86,3505.14)
MOTOR2_LOUT: CN3.10 U9.8 | length 488.1
  Top Layer w20: U9.8@4354.08,3925.77 4354.08,3945.92 4327.03,3972.97 4327.03,4122.03 4369.02,4164.02 4489.02,4164.02 4519.02,4194.02 CN3.10@4519.02,4252.8
MOTOR3_H: U2.42 U10.3@4774.08,3696.81 | length 2194.7
  Top Layer w6: U10.3@4774.08,3696.81 4782.2,3688.7 v1(4782.2,3656.96) ; v1(6696.08,3483.92) 6701.19,3489.03 U2.42@6701.19,3618.64
  Bottom Layer w6: v1(4782.2,3656.96) 5047.8,3656.96 5082.91,3692.08 6224.58,3692.08 6271.36,3645.3 6441.8,3645.3 6603.18,3483.92 v1(6696.08,3483.92)
MOTOR3_HOUT: CN4.9 U10.6@4774.08,3925.81 | length 1060
  Top Layer w20: v2(4745,4022.34) 4748.1,4019.24 4748.1,3961.9 4774.08,3935.92 U10.6@4774.08,3925.81 ; v2(5370,4145) 5515,4145 5570.2,4200.2 CN4.9@5570.2,4252.8
  Bottom Layer w20: v2(4745,4022.34) 4867.66,4145 v2(5370,4145)
MOTOR3_L: U2.43 U10.2@4724.08,3696.81 | length 2316.7
  Top Layer w6: U10.2@4724.08,3696.81 4724.08,3646 4731.67,3638.41 v1(4758.33,3638.41) ; v1(6716.07,3461.36) 6720.87,3466.16 U2.43@6720.87,3618.64
  Bottom Layer w6: v1(4758.33,3638.41) 4760.76,3635.97 5040.97,3635.97 5087.06,3682.06 6220.43,3682.06 6267.21,3635.28 6437.65,3635.28 6611.58,3461.36 v1(6716.07,3461.36)
MOTOR3_LOUT: CN4.10 U10.8@4674.08,3925.81 | length 1054
  Top Layer w20: v2(4640,3970) 4674.08,3935.92 U10.8@4674.08,3925.81 ; v2(5335,4180) 5465,4180 5491.46,4206.46 CN4.10@5491.46,4252.8
  Bottom Layer w20: v2(4640,3970) 4644.6,3970 4843.61,4169.02 5324.02,4169.02 v2(5335,4180)
MOTOR4_H: U2.45 U11.3 | length 1965
  Top Layer w6: U11.3@5094.08,3696.73 5102.2,3688.62 v1(5102.2,3656.88) ; U2.45@6760.24,3618.64 6761.55,3617.33 v1(6761.55,3495.99)
  Bottom Layer w6: v1(5102.2,3656.88) 5117.36,3672.05 6216.28,3672.05 6263.06,3625.27 6433.5,3625.27 6618.4,3440.37 6729.76,3440.37 6761.55,3472.16 v1(6761.55,3495.99)
MOTOR4_HOUT: CN5.9 U11.6 | length 1703.9
  Top Layer w20: v2(5065,4010) 5065,3965 5094.08,3935.92 U11.6@5094.08,3925.73 ; v2(6301.53,4123.47) 6328.06,4150 6490,4150 6542.64,4202.64 CN5.9@6542.64,4252.8
  Bottom Layer w20: v2(5065,4010) 5140,4085 5410,4085 5448.47,4123.47 v2(6301.53,4123.47)
MOTOR4_L: U2.46 U11.2 | length 2062.7
  Top Layer w6: U11.2@5044.08,3696.73 5044.08,3645.92 5050,3640 v1(5075,3640) ; U2.46@6779.93,3618.64 6784.45,3614.12 v1(6784.45,3515.52)
  Bottom Layer w6: v1(5075,3640) 5079.11,3635.89 5110.89,3635.89 5137.03,3662.03 6212.13,3662.03 6258.91,3615.25 6429.36,3615.25 6614.25,3430.35 6733.91,3430.35 6784.45,3480.89 v1(6784.45,3515.52)
MOTOR4_LOUT: CN5.10 U11.8 | length 1692.2
  Top Layer w20: v2(4965,3965) 4994.08,3935.92 U11.8@4994.08,3925.73 ; v2(6295,4170) 6310,4185 6435,4185 6463.9,4213.9 CN5.10@6463.9,4252.8
  Bottom Layer w20: v2(4965,3965) 4971.94,3965 5115.95,4109.02 5394.02,4109.02 5432.49,4147.49 6272.49,4147.49 v2(6295,4170)
MOTOR_HOUT: CN2.9@4062.29,5349.97 CN2.9@6388.09,6460.26 U4.1@3859.6,6436.12 U4.1@6590.78,5374.11 | length 5177
  Top Layer w20: CN2.9@4062.29,5349.97 4072.29,5359.97 v3(4235.07,5359.97) v3(4285.07,5359.97) ; v3(6165.31,6450.26) v3(6215.31,6450.26) 6378.09,6450.26 CN2.9@6388.09,6460.26
  Bottom Layer w20: U4.1@3859.6,6436.12 3873.74,6450.26 v3(6165.31,6450.26) v3(6215.31,6450.26) ; v3(4235.07,5359.97) v3(4285.07,5359.97) 6576.64,5359.97 U4.1@6590.78,5374.11
MOTOR_LOUT: CN2.10@4062.29,5271.23 CN2.10@6388.09,6539 U5.1@3965.66,6330.05 U5.1@6484.72,5480.18 | length 5198.2
  Top Layer w20: CN2.10@4062.29,5271.23 4071.37,5280.31 4135.07,5280.31 4160.72,5305.96 ; 4160.07,5305.96 4160.72,5305.96 ; v3(4254.42,5325.31) 4205.72,5325.31 v3(4205.07,5325.96) 4180.72,5325.96 4160.72,5305.96 ; v3(6195.96,6484.93) 6244.66,6484.93 v3(6245.31,6484.28) 6269.66,6484.28 6289.66,6504.28 ; 6290.31,6504.28 6289.66,6504.28 ; CN2.10@6388.09,6539 6379.01,6529.93 6315.31,6529.93 6289.66,6504.28
  Bottom Layer w20: U5.1@3965.66,6330.05 4061.85,6426.24 6144.09,6426.24 6155.41,6414.93 6225.21,6414.93 6247.29,6437.01 6247.29,6482.29 v3(6245.31,6484.28) ; v3(4205.07,5325.96) 4203.09,5327.94 4203.09,5373.22 4225.17,5395.31 4294.97,5395.31 4306.29,5383.99 6388.53,5383.99 U5.1@6484.72,5480.18
NRST: C6.2@6969.29,3760.93 RN3.4 SW1.1 U2.7 | length 933.3
  Top Layer w6: RN3.4@6654.38,4055.5 6654.87,4055 v1(6685,4055) ; v1(6725,3825) 6824.41,3825 6853.6,3795.8 U2.7@6878.35,3795.8 6933.62,3795.8 6968.49,3760.93 C6.2@6969.29,3760.93 6995.99,3734.23 7055.77,3734.23 7090,3700 SW1.1@7090,3470
  Bottom Layer w6: v1(6685,4055) 6715.26,4024.74 6715.26,3889.39 6704.29,3878.42 6704.29,3845.71 v1(6725,3825)
RGB_OUT: CN2.4@4062.29,5743.67 CN2.4@6388.09,6066.56 LED1.4@4872.12,6545.52 LED1.4@5578.26,5264.71 RGB.1 | length 4395.9
  Top Layer w6: LED1.4@4872.12,6545.52 v1(4950.31,6545.51) ; v1(5500.07,5264.73) LED1.4@5578.25,5264.73
  Top Layer w20: v1(3925.07,5743.67) v1(3960.07,5743.67) CN2.4@4062.29,5743.67 ; CN2.4@6388.09,6066.56 v1(6490.31,6066.56) v1(6525.31,6066.56)
  Bottom Layer w10: v1(3960.07,5743.67) 4106.06,5597.69 4106.06,5324.56 4156.32,5274.31 5490.49,5274.31 v1(5500.07,5264.73) ; v1(4950.31,6545.51) 4959.89,6535.93 6294.07,6535.93 6344.32,6485.67 6344.32,6212.54 v1(6490.31,6066.56)
  Bottom Layer w20: RGB.1@3876.06,5744.05 3876.44,5743.67 v1(3925.07,5743.67) v1(3960.07,5743.67) ; v1(6490.31,6066.56) v1(6525.31,6066.56) 6573.94,6066.56 RGB.1@6574.32,6066.18
RGB_OUT1: CN2.4@4019.02,4252.8 U2.18 | length 4862
  Top Layer w6: CN2.4@4019.02,4252.8 v1(4019.02,4433.39) ; v1(6651.29,3693.45) 6700,3742.16 6700,3874.13 6720.87,3895 U2.18@6720.87,3953.28
  Bottom Layer w6: v1(4019.02,4433.39) 4141.81,4433.39 4180.91,4472.49 4455.21,4472.49 4485.26,4442.44 4950,4442.44 5002,4494.44 5239.67,4494.44 5261.62,4472.49 5919.09,4472.49 5971.09,4524.49 6225.41,4524.49 6247.36,4502.53 7028.81,4502.53 7131.91,4399.44 7131.91,4138.55 7101.16,4107.81 7101.16,3916.16 7072.17,3887.17 7072.17,3819.42 6862.34,3609.59 6756.57,3609.59 6672.71,3693.45 v1(6651.29,3693.45)
RGB_OUT2: CN3.4 U2.19 | length 3853.9
  Top Layer w6: CN3.4@4991.46,4252.8 v1(4991.46,4453.42) ; v1(6629.86,3714.45) 6689.98,3774.57 6689.98,3879.15 6701.19,3890.35 U2.19@6701.19,3953.28
  Bottom Layer w6: v1(4991.46,4453.42) 5002.44,4442.44 5082.21,4442.44 5124.19,4484.42 5235.52,4484.42 5257.48,4462.47 5923.23,4462.47 5975.23,4514.47 6221.26,4514.47 6243.21,4492.52 7024.66,4492.52 7121.89,4395.29 7121.89,4142.7 7091.15,4111.95 7091.15,3921.15 7062.16,3892.16 7062.16,3823.57 6858.19,3619.6 6760.72,3619.6 6665.88,3714.45 v1(6629.86,3714.45)
RGB_OUT3: CN4.4 U2.29 | length 2983.7
  Top Layer w6: CN4.4@5963.9,4252.8 v1(5963.9,4473.45) ; v1(6411.01,3821.77) 6433.54,3799.23 6502.71,3799.23 6518.96,3815.49 U2.29@6543.71,3815.49
  Bottom Layer w6: v1(5963.9,4473.45) 5974.88,4462.47 6061.19,4462.47 6103.17,4504.46 6217.11,4504.46 6239.06,4482.5 7020.51,4482.5 7111.87,4391.14 7111.87,4146.84 7081.13,4116.1 7081.13,3926.13 7052.14,3897.14 7052.14,3827.72 6854.04,3629.62 6764.87,3629.62 6659.05,3735.44 6486.3,3735.44 6411.01,3810.74 v1(6411.01,3821.77)
RGB_OUT4: CN5.4 U2.32 | length 1276.4
  Top Layer w6: v1(6495,3756.43) U2.32@6543.71,3756.43 ; CN5.4@6936.34,4252.8 6936.34,4203.66 6970,4170 7061.51,4170 v1(7083.43,4148.08)
  Bottom Layer w6: v1(6495,3756.43) 6652.22,3756.43 6769.02,3639.64 6849.9,3639.64 7042.13,3831.87 7042.13,3902.13 7071.12,3931.12 7071.12,4135.77 v1(7083.43,4148.08)
RS485_A: R8.1 U7.6 | length 742.7
  Top Layer w6: U7.6@5716.82,3520 v1(5795,3520)
  Top Layer w10: v1(5174.21,3500) R8.1@5199.66,3500 ; U7.6@5715.62,3518.8 U7.6@5716.82,3520
  Bottom Layer w10: v1(5174.21,3500) 5184.21,3490 5765,3490 v1(5795,3520)
RS485_B: R7.1 U7.7 | length 742.7
  Top Layer w6: U7.7@5715.62,3468.8 v1(5795,3468.8)
  Top Layer w10: v1(5174.21,3430) R7.1@5199.66,3430
  Bottom Layer w10: v1(5174.21,3430) 5214.21,3470 5793.8,3470 v1(5795,3468.8)
SWCLK: H2.2 U2.37 | length 728.8
  Top Layer w6: U2.37@6602.76,3618.64 6602.76,3667.76 v1(6605.16,3670.16)
  Bottom Layer w6: v1(6605.16,3670.16) 6612.87,3662.45 6673.84,3662.45 6681.39,3654.89 6682.94,3654.89 6748.28,3589.56 6870.64,3589.56 7091.08,3810 7111.8,3810 H2.2@7143.61,3841.82
SWIO: H2.1 U2.34 | length 828.5
  Top Layer w6: U2.34@6543.71,3717.06 6597.18,3717.06 v1(6599.86,3714.38)
  Bottom Layer w6: v1(6599.86,3714.38) 6641.78,3672.46 6679.54,3672.46 6752.42,3599.57 6866.49,3599.57 7082.19,3815.27 7082.19,3880.39 H2.1@7143.61,3941.82
SYS_RGB: LED1.4@3497.61,3509.03 U2.6 | length 4580.7
  Top Layer w6: LED1.4@3497.61,3509.03 3509.03,3509.03 3545,3545 3730,3545 3750,3525 3750,3410 3775,3385 4079.47,3385 4115,3420.53 4115,3583.32 v1(4148.69,3617.01) ; v1(6578.42,3595.03) 6584.16,3600.78 6584.16,3679.16 6598.39,3693.39 6621.67,3693.39 6642.6,3672.46 6667.46,3672.46 6710.02,3715.02 6710.02,3775.02 6745,3810 6810,3810 6843.88,3776.12 U2.6@6878.35,3776.12
  Bottom Layer w6: v1(4148.69,3617.01) 4149.09,3617.42 5106.58,3617.42 5141.18,3652.02 6207.98,3652.02 6254.77,3605.23 6425.21,3605.23 6610.11,3420.34 6738.06,3420.34 6805.44,3487.72 6805.44,3524.56 6790.52,3539.48 6725.99,3539.48 6670.44,3595.03 v1(6578.42,3595.03)
pads on no net: CN2.11 CN2.12 CN3.11 CN3.12 CN4.11 CN4.12 CN5.11 CN5.12 LED1.2@3694.46,3627.13 LED2.2 TP1.1 TP2.1 TP3.1 TP5.1 U1.3@4619.22,5138.02 U1.3@5831.16,6672.22 U1.5@5735.24,3880

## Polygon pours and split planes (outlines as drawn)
GND on Top Layer (solid, remove dead copper, pour order 0): 3000,7240 7595,7240 7595,3140 3000,3140
GND on Bottom Layer (solid, remove dead copper, pour order 2): 3375,7365 7390,7365 7390,3000 3375,3000

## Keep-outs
Top Layer:
  region: 4180,3594.39 4180,3707.89 5144.08,3707.89 5144.08,3594.39
  region: 5467.5,3621.73 5467.5,4128.16 6178.28,4128.16 6178.28,3621.73
  region: 6530.75,4023.57 6530.75,4154.83 7012.08,4154.83 7012.08,4025 7010,4025 7010,4023.57
Board Outline Layer:
  region: 6268.44,3773.36 6268.44,3593.69 6540.56,3593.69 6540.56,3536.18 7075.81,3536.18 7075.81,4026.08 6537.79,4026.08 6537.79,3945.79 6440.87,3945.79
  lines w10: 4483.74,5615 6391.34,5615 6391.34,5686.34 6305.47,5686.34 cw(c6305.47,5765.08) 6249.79,5709.4 6153.36,5805.83 cw(c6209.04,5861.51) 6130.3,5861.51 6130.3,6031.27 ccw(c6051.56,6031.27) 6107.23,6086.95 6022.32,6171.86 ccw(c5966.65,6116.19) 5966.65,6194.93 4055,6194.93 4055,6123.9 4140.05,6123.9 cw(c4140.23,6033.36) 4200.59,6100.83 4297.02,6004.41 cw(c4241.34,5948.73) 4320.08,5948.73 4320.08,5778.96 ccw(c4398.82,5778.96) 4343.15,5723.28 4428.06,5638.37 ccw(c4483.74,5694.05) 4483.74,5615.31 ; 5039.44,4805 5240,4805 5240,4570 4877.35,4570 4877.35,4631.34 4960.7,4631.34 ccw(c4960.7,4670.71) 5000.07,4670.71 5000.07,4765.94 cw(c5039.44,4765.94) 5039.44,4805.31 ; 3400,3379.37 3400,4530.63 cw(c3439.37,4530.63) 3439.37,4570 4820,4570 4820.09,4631.34 4744.44,4631.34 cw(c4744.44,4670.71) 4705.07,4670.71 4705.07,4765.94 ccw(c4665.7,4765.94) 4665.7,4805.31 4178.25,4805.31 cw(c4178.25,4884.05) 4122.58,4828.37 4058.14,4892.81 ccw(c4002.46,4837.13) 4002.46,4915.87 3784.28,4915.87 cw(c3784.28,4994.61) 3705.54,4994.61 3705.54,6045.16 cw(c3784.28,6045.16) 3784.28,6123.9 3990.88,6124.16 3990.88,6194.93 cw(c3990.88,6273.67) 3935.2,6217.99 3718.61,6434.58 cw(c3774.28,6490.26) 3695.54,6490.26 3695.54,6965.56 cw(c3734.91,6965.56) 3734.91,7004.93 3858.89,7004.93 cw(c3858.89,6965.56) 3898.26,6965.56 3898.26,6679.33 ccw(c3977,6679.33) 3921.32,6623.65 3969.52,6575.46 ccw(c4025.19,6631.14) 4025.19,6552.4 4480.16,6552.4 ccw(c4480.16,6631.14) 4535.84,6575.46 4584.04,6623.65 ccw(c4528.36,6679.33) 4607.1,6679.33 4607.1,6926.19 cw(c4685.84,6926.19) 4685.84,7004.93 5410.94,7004.93 ccw(c5410.94,7044.3) 5450.31,7044.3 5450.31,7139.53 cw(c5489.68,7139.53) 5489.68,7178.9 5705.94,7178.9 cw(c5705.94,7139.53) 5745.31,7139.53 5745.31,7044.3 ccw(c5784.68,7044.3) 5784.68,7004.93 6272.13,7004.93 cw(c6272.13,6926.19) 6327.81,6981.86 6392.24,6917.42 ccw(c6447.92,6973.1) 6447.92,6894.36 6666.1,6894.36 cw(c6666.1,6815.62) 6744.84,6815.62 6744.84,5765.08 cw(c6666.1,5765.08) 6666.1,5686.34 6441.18,5686.34 6441.18,5615.31 6459.51,5615.31 cw(c6459.51,5536.57) 6515.18,5592.24 6731.77,5375.65 cw(c6676.1,5319.98) 6754.84,5319.98 6754.84,4844.68 cw(c6715.47,4844.68) 6715.47,4805.31 6591.49,4805.31 cw(c6591.49,4844.68) 6552.12,4844.68 6552.12,5130.9 ccw(c6473.38,5130.9) 6529.06,5186.58 6480.86,5234.77 ccw(c6425.19,5179.1) 6425.19,5257.84 5970.22,5257.84 ccw(c5970.22,5179.1) 5914.54,5234.77 5866.35,5186.58 ccw(c5922.02,5130.9) 5843.28,5130.9 5843.28,4884.05 cw(c5764.54,4884.05) 5764.54,4805.31 5285,4805.31 5285,4570 7280.63,4570 cw(c7280.63,4530.63) 7320,4530.63 7320,3379.37 cw(c7280.63,3379.37) 7280.63,3340 3439.37,3340 cw(c3439.37,3379.37) 3400,3379.37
